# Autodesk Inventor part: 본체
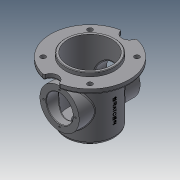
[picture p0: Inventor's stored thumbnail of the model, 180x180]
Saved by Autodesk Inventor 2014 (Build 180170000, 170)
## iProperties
Created: 2018-04
Part Number: 본체
Material: 일반
Document SubType Name: Modeling
Designer: NET
Density: 1 g/cm^3
Appearance: 기본값
Mass: 424.295 g
Surface Area: 1204.04 cm^2
Volume: 424.295 cm^3
Author: NET
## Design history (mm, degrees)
sketch "스케치1"
  geometry: C1 r 80 at (0, 0); 1 further point
  constraints: 1 centre point, 1 coincident
  dimensions: "d0" = 160 diameter of C1
extrude "돌출1" new body sketch "스케치1" distance "d1" = 10; taper "d2" = 0 deg
sketch "스케치2"
  geometry: C1 r 80 at (0, 0) reference; C2 r 50 at (0, 0)
  constraints: 1 centre point, 1 coincident
  dimensions: "d3" = 100 diameter of C2
extrude "돌출2" join sketch "스케치2" distance "d4" = 8; taper "d5" = 0 deg
sketch "스케치3"
  geometry: C1 r 80 at (0, 0) reference; C2 r 50 at (0, 0)
  constraints: 1 centre point, 1 coincident
  dimensions: "d6" = 100 diameter of C2
extrude "돌출3" join sketch "스케치3" distance "d7" = 110; taper "d8" = 0 deg
sketch "스케치4"
  geometry: C1 r 50 at (0, 0) reference; C2 r 40 at (0, 0)
  constraints: 1 centre point, 1 coincident
  dimensions: "d9" = 80 diameter of C2
extrude "돌출4" join sketch "스케치4" distance "d10" = 5; taper "d11" = 0 deg
node "작업 평면1"
sketch "스케치5"
  geometry: L1 (80, 10)-(-80, 10) reference; C1 r 40 at (0, -50); 1 further point
  constraints: 1 centre point, 1 vertical alignment
  dimensions: "d13" = 80 diameter of C1; "d14" = 60 distance from line of C1.centre L1
extrude "돌출5" join sketch "스케치5" stored distance "d15" = 5; taper "d16" = 0 deg
sketch "스케치6"
  geometry: C1 r 50 at (0, 0) reference; C2 r 45 at (0, 0)
  constraints: 1 centre point, 1 coincident
  dimensions: "d17" = 90 diameter of C2
extrude "돌출6" cut sketch "스케치6" distance "d18" = 120; taper "d19" = 0 deg
sketch "스케치7"
  geometry: C1 r 40 at (0, 0) reference; C2 r 27 at (0, 0); 1 further point
  constraints: 1 centre point, 1 coincident
  dimensions: "d20" = 54 diameter of C2
extrude "돌출7" cut sketch "스케치7" distance "d21" = 40; taper "d22" = 0 deg
sketch "스케치8" dims "d23" = 65
  geometry: C1 r 27 at (0, 0) reference; C2 r 40 at (0, 0) reference; C3 r 2 at (0, 32.5); 2 further points
  constraints: 2 vertical alignment, 1 centre point, 1 coincident, 2 other
  dimensions: "d24" = 4 diameter of C3
hole "구멍1" sketch "스케치8" at (0, 32.5) diameter "d25" = 3.242; stored, may be unused: countersink angle "d29" = 90 deg, drill point angle "d31" = 118 deg; dims "d26" = 8, "d27" = 4, "d28" = 2, "d30" = 10
sketch "스케치9"
  geometry: C1 r 40 at (0, 0) reference; C2 r 27 at (0, 0)
  constraints: 1 centre point, 1 coincident
  dimensions: "d35" = 54 diameter of C2
extrude "돌출8" cut sketch "스케치9" distance "d36" = 13; taper "d37" = 0 deg
sketch "스케치10" dims "d38" = 65
  geometry: C1 r 27 at (0, 0) reference; C2 r 40 at (0, 0) reference; C3 r 2 at (0, 32.5); 1 further point
  constraints: 2 vertical alignment, 1 centre point, 1 coincident, 2 other
  dimensions: "d39" = 4 diameter of C3
hole "구멍2" sketch "스케치10" at (0, 32.5) diameter "d40" = 3.242; stored, may be unused: countersink angle "d44" = 90 deg, drill point angle "d46" = 118 deg; dims "d41" = 8, "d42" = 4, "d43" = 2, "d45" = 10
sketch "스케치11" dims "d50" = 135
  geometry: L1 (0, 0)-(-71.606, 71.606); L2 (0, 0)-(0, 105.551); C1 r 80 at (0, 0) reference; C2 r 5 at (-47.73, 47.73)
  constraints: 4 end point, 1 centre point, 1 coincident, 1 point on line, 1 vertical, 3 other
  dimensions: "d51" = 45 deg angle of L1 L2; "d52" = 10 diameter of C2
extrude "돌출9" cut sketch "스케치11" distance "d53" = 10; taper "d54" = 0 deg
node "작업 평면2"
sketch "스케치12"
  geometry: C1 r 50 at (0, 0) reference; C2 r 15 at (0, 80); C3 r 15 at (0, -80); A1 r 80 centre (0, 0) between (0, 80) and (0, -80) reference; A2 r 80 centre (0, 0) between (0, 80) and (0, -80) reference
  constraints: 4 point on circle, 2 centre point, 2 vertical alignment
  dimensions: "d72" = 30 diameter of C2; "d73" = 30 diameter of C3
sketch "스케치13"
  geometry: L1 (0, 10)-(0, 10) reference; 2 further points
  constraints: 1 other
  dimensions: "d63" = 70 distance from line of L1 point (0, -60)
feature "엠보싱1" sketch "스케치13" dims "d1" = 10, "d64" = 0.5, "d65" = 0
chamfer "모따기1" distance "d66" = 1; stored, may be unused: second distance "d67" = 2, angle "d68" = 45 deg
fillet "모깎기1" dims "d69" = 5
fillet "모깎기2" dims "d70" = 3
fillet "모깎기3" dims "d71" = 3
extrude "돌출11" cut sketch "스케치12" distance "d74" = 10; taper "d75" = 0 deg
fillet "모깎기4" dims "d76" = 3
node "솔리드1"
mirror "대칭1"
pattern_circular "원형 패턴1" dims angle "d33" = 360 deg
mirror "대칭2"
pattern_circular "원형 패턴2" dims angle "d48" = 360 deg
pattern_circular "원형 패턴3" dims angle "d56" = 360 deg
other parameters: "d12" = 62
